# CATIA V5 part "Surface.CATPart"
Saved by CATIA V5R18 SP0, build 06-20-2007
Part number: Part1
Bounding box of the stored display mesh (mm): x -50 to 50, y 0 to 200, z 0 to 79.597
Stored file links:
  D:\shriniwas\v5_r19\c16_CAT_v5r19\c16_Part\Point Surface Joint\Surface.CATPart
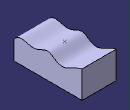
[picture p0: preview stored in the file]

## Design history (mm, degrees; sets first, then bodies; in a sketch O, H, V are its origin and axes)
Body1 (main body)
  Sketch1 on yz-plane, origin (0, 0, 0), H (0, 1, 0), V (0, 0, 1)
    spline S1 through (0, 52.7587) (16.6889, 67.1156) (74.2459, 65.3633) (97.6382, 74.1545) (129.8025, 59.0839) (168.2327, 66.2006) (200, 79.5967)
    line L1 (0, 52.7587) -> (0, 0)
    point P1 (0, 52.7587)
    point P2 (0, 0)
    line L2 (0, 0) -> (200, 0)
    line L3 (200, 0) -> (200, 79.5967)
    point P4 (200, 79.5967)
    point P5 (0, 52.7587)
    point P6 (200, 79.5967)
    length L2 = 200
    coincidence: P5 P1, P2 H, P6 P4, L1 V
    vertical: L1 V, L3 V
    horizontal: L2 H
  Pad1: profile Sketch1, direction (1, 0, 0), length 50, mirrored extent
  Point1: type OnSurface, Support face of Pad1 from Sketch1.S1, Direction (0.8882, 0.2225, -0.4019), Length 0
